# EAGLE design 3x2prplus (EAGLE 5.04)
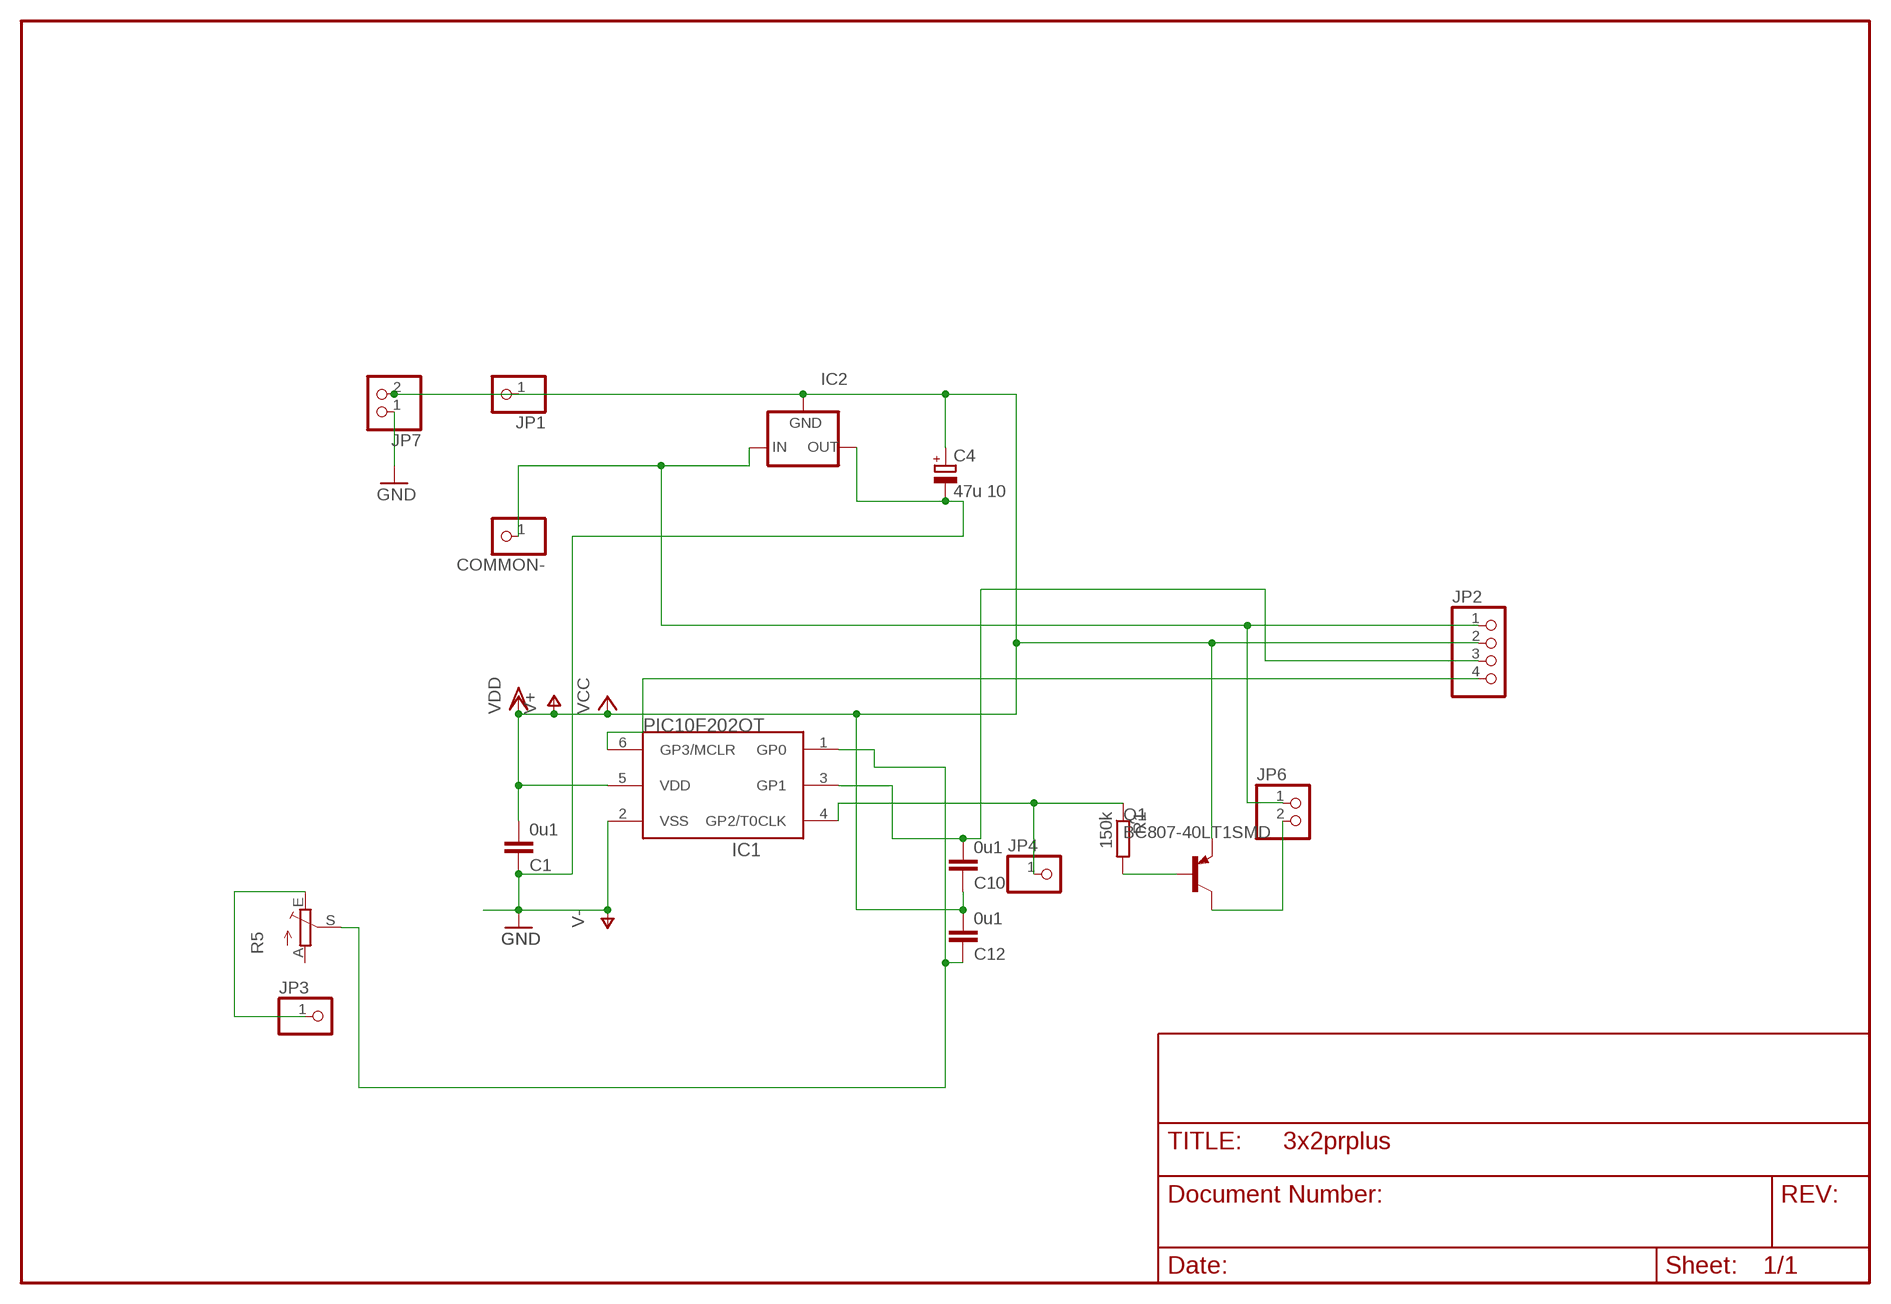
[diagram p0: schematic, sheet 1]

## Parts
C1  0u1  C-EUC1206  [C1206]
C4  47u 10  CPOL-EUE2.5-6  [E2,5-6]
C10  0u1  C-EUC0805  [C0805]
C12  0u1  C-EUC0805  [C0805]
COMMON-  PINHD-1X1  [1X01]
IC1  PIC10F202OT  [SOT23-6]
IC2  79LXX  [79LXX]
JP1  PINHD-1X1  [1X01]
JP2  PINHD-1X4  [1X04]
JP3  PINHD-1X1  [1X01]
JP4  PINHD-1X1  [1X01]
JP6  PINHD-1X2  [1X02]
JP7  PINHD-1X2  [1X02]
Q1  BC807-40LT1SMD  [SOT23-BEC]
R1  150k  R-EU_R0805  [R0805]
R5  TRIM_EU-CA6V  [CA6V]

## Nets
GND: C1.1 C4.- IC1.2(VSS) IC2.OUT JP7.1 ; supply symbol labelled V-
N$1: C10.2 IC1.3(GP1) JP2.3
N$2: Q1.B R1.2
N$3: IC1.6(GP3/MCLR) JP2.4
N$4: JP6.2 Q1.C
N$5: IC1.4(GP2/T0CLK) JP4.1 R1.1
N$7: JP3.1 R5.E
N$8: COMMON-.1 IC2.IN JP2.1 JP6.1
N$13: C12.1 IC1.1(GP0) R5.S
V+: C1.2 C4.+ C10.1 C12.2 IC1.5(VDD) IC2.GND JP1.1 JP2.2 JP7.2 Q1.E ; supply symbol labelled VCC, VDD
Unconnected: R5.A

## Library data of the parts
C1 C10 C12 = rcl:C-EU: CAPACITOR, European symbol
C4 = rcl:CPOL-EU: POLARIZED CAPACITOR, European symbol
COMMON- JP1 JP3 JP4 = pinhead:PINHD-1X1: PIN HEADER
IC1 = microchip-5:PIC10F20*: uPC nW 0,25/0,5k Program Flash memory
IC2 = v-reg:79LXX: VOLTAGE REGULATOR
JP2 = pinhead(2):PINHD-1X4: PIN HEADER
JP6 JP7 = pinhead:PINHD-1X2: PIN HEADER
Q1 = transistor-pnp:BC807*: PNP Transistror
R1 = rcl:R-EU_: RESISTOR, European symbol
R5 = pot:TRIM_EU-: POTENTIOMETER

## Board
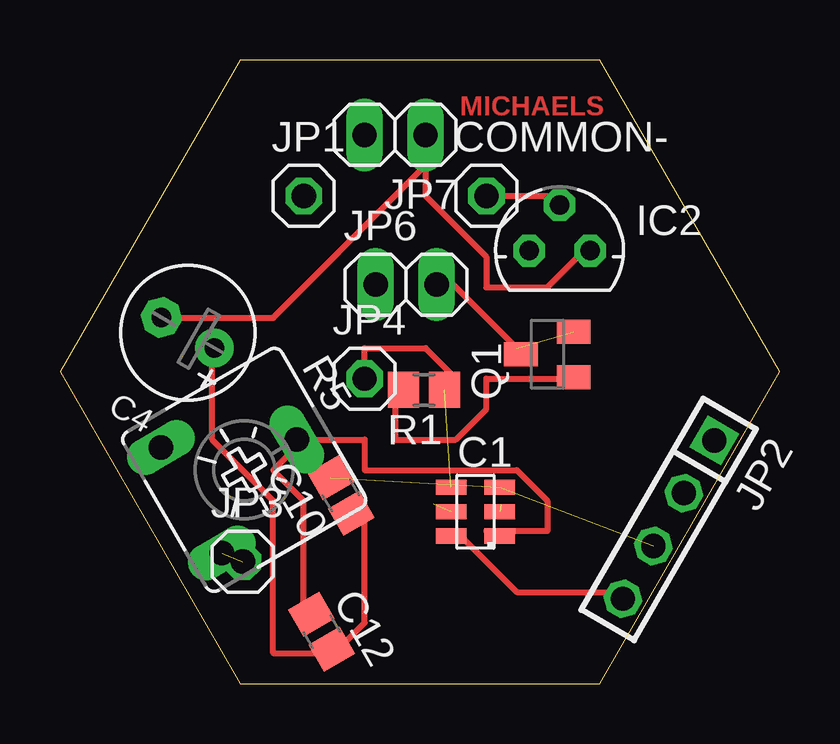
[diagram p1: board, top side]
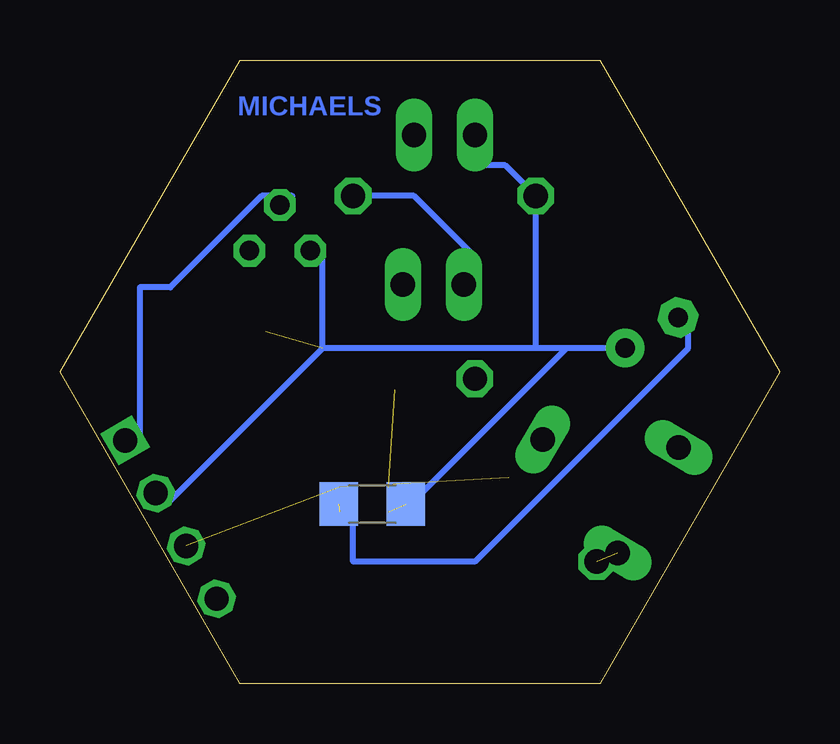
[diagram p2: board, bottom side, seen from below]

Size 30 x 25.98 mm. Coordinates in mm from the lower left corner, seen from the top.
Outline: 7.5,0 22.5,0 30,12.99 22.5,25.98 7.5,25.98 0,12.99 7.5,0
Copper layers (1*16): Top 0.035mm / dielectric 1.5mm / Bottom 0.035mm
Design rules "default *": minimum track width 10mil, minimum drill 24mil, track to track 8mil, track to pad 8mil, pad to pad 8mil, via to via 8mil, smd to smd 8mil, copper to edge 10mil, drill to drill 8mil, minimum pad ring 10mil, minimum via ring 8mil, stop-mask expansion 4mil, vias tented up to drill 0mil, thermal gap 10mil

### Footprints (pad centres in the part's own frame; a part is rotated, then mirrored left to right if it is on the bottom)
C1206 = smd 1.6 x 1.8: 1 -1.4,0; 2 1.4,0
E2,5-6 = drill 0.813 pad 1.6 round: + -1.27,0 | drill 0.813 pad 1.6 octagon: - 1.27,0
C0805 = smd 1.3 x 1.5: 1 -0.85,0; 2 0.85,0
1X01 = drill 1.016 octagon: 1 0,0
SOT23-6 = smd 0.635 x 1.27: 1 -1.016,-1.016; 2 0,-1.016; 3 1.016,-1.016; 4 1.016,1.016; 5 0,1.016; 6 -1.016,1.016
79LXX = drill 0.813 octagon: GND -1.27,0; IN 0,1.905; OUT 1.27,0
1X04 = drill 1.016 square: 1 -3.81,0 | drill 1.016 octagon: 2 -1.27,0; 3 1.27,0; 4 3.81,0
1X02 = drill 1.016 long: 1 -1.27,0; 2 1.27,0
SOT23-BEC = smd 1 x 1.4: B -0.95,-1.1; C 0,1.1; E 0.95,-1.1
R0805 = smd 1.3 x 1.5: 1 -0.85,0; 2 0.85,0
CA6V = drill 1.016 long: A -2.54,-2.54; E 2.54,-2.54; S 0,2.54

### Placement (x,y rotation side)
C1  16.98,7.48 0 bottom
C4  5.33,14.62 150 top
C10  11.72,7.83 120 top
C12  10.91,2.16 300 top
COMMON-  17.78,20.32 0 top
IC1  17.32,7.16 90 top
IC2  20.83,18.03 0 top
JP1  10.16,20.32 0 top
JP2  25.38,6.83 240 top
JP3  7.62,5.08 0 top
JP4  12.7,12.7 0 top
JP6  14.43,16.62 0 top
JP7  13.97,22.86 180 top
Q1  20.32,13.72 90 top
R1  15.18,12.24 180 top
R5  7.68,8.9 300 top

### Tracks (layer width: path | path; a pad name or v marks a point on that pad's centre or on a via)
GND  (1 unrouted)
  Top 0.254: 15.24,21.59 15.24,20.32 17.78,17.78 17.78,16.51 20.32,16.51 21.59,17.78 IC2.OUT | 15.24,21.59 8.89,15.24 3.81,15.24 C4.- | 15.24,21.59 JP7.1
  Bottom 0.254: C1.1 17.78,7.62 17.78,5.08 12.7,5.08 3.81,13.97 3.81,15.24 C4.-
N$1  (2 unrouted)
N$2
  Top 0.254: Q1.B 21.59,12.7 17.78,12.7 17.78,11.43 16.51,10.16 13.97,10.16 13.97,12.7 R1.2
N$3
  Top 0.254: IC1.6 16.51,6.35 19.05,3.81 22.86,3.81 JP2.4
N$4
  Top 0.254: Q1.C 19.05,13.97 15.24,17.78 JP6.2
N$5  (1 unrouted)
  Top 0.254: JP4.1 12.7,13.97 15.24,13.97 16.51,12.7 R1.1
N$7  (1 unrouted)
N$8
  Top 0.254: COMMON-.1 20.32,20.32 IC2.IN
  Bottom 0.254: COMMON-.1 15.24,20.32 12.7,17.78 JP6.1 | JP2.1 26.67,10.16 26.67,16.51 25.4,16.51 21.59,20.32 20.32,20.32 IC2.IN
N$13
  Top 0.254: 10.16,10.16 12.7,10.16 12.7,8.89 19.05,8.89 20.32,7.62 20.32,6.35 17.78,6.35 IC1.1 | 10.16,10.16 8.89,8.89 10.16,7.62 10.16,2.54 C12.1 | 10.16,10.16 R5.S
V+  (2 unrouted)
  Top 0.254: 11.43,1.27 12.7,2.54 12.7,7.62 C10.1 | 11.43,1.27 8.89,1.27 8.89,7.62 6.35,10.16 6.35,13.97 C4.+ | 11.43,1.27 C12.2
  Bottom 0.254: JP7.2 12.7,21.59 11.43,21.59 JP1.1 10.16,13.97 | 8.89,13.97 15.24,7.62 C1.2 | 8.89,13.97 6.35,13.97 C4.+ | 19.05,13.97 19.05,17.78 IC2.GND | 8.89,13.97 10.16,13.97 | 10.16,13.97 19.05,13.97 | 19.05,13.97 25.4,7.62 JP2.2

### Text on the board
Top: MICHAELS
Bottom: MICHAELS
